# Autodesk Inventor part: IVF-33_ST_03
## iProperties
Created: 2008-10
Part Number: IVF-33_ST_03
Material: 3.3206  AlMgSi 0.5  H22
Document SubType Name: Blech
Designer: Gawin
Density: 2.66 g/cm^3
Mass: 817.313 g
Surface Area: 3076.75 cm^2
Volume: 307.261 cm^3
Stock Number: IVF-33_ST_03
Author: Gawin
